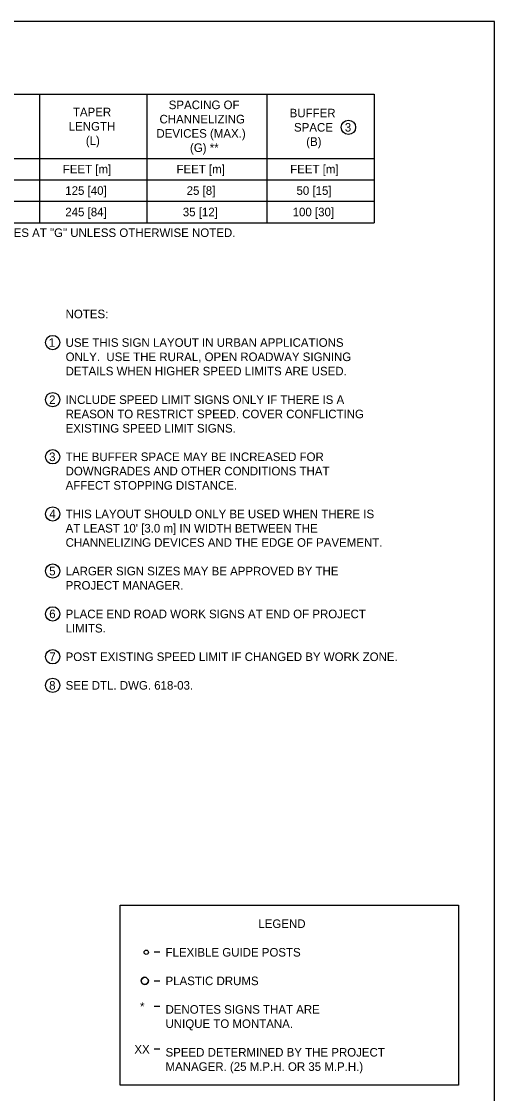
# Model space of a CAD drawing. Extents: x 49991.4 to 50021, y 49987.6 to 50011.4.
# Drawn here: x 50005.31 to 50008.61, y 50003.76 to 50011.26 of the extents above; entities that cross this region are included whole.
import ezdxf

# ---------------------------------------------------------------- set-up
doc = ezdxf.new("R2010")
doc.units = 0
doc.layers.add('Level 1', color=7, linetype='Continuous')
doc.layers.add('Level 2', color=7, linetype='Continuous')

msp = doc.modelspace()

# ---------------------------------------------------------------- linework, layer by layer
at = {"layer": 'Level 1'}
msp.add_lwpolyline([(50008.6146, 50011.2628), (50000.3356, 50011.2628), (50000.3356, 50000.0624), (50008.6146, 50000.0624)], close=True, dxfattribs=at)
for centre, radius in [((50006.1788, 50004.7458), 0.015), ((50006.1688, 50004.5458), 0.025)]:
    msp.add_circle(centre, radius, dxfattribs=at)
for start, end in [(360, 180), (180, 0)]:
    msp.add_arc((50006.1688, 50004.5458), 0.025, start, end, dxfattribs=at)
at = {"layer": 'Level 2'}
for p, q in [((50003.8428, 50010.7538), (50007.7728, 50010.7538)), ((50005.4328, 50010.7538), (50005.4328, 50009.8538)), ((50006.1828, 50010.7538), (50006.1828, 50009.8538)), ((50007.0228, 50010.7538), (50007.0228, 50009.8538)), ((50007.7728, 50010.7538), (50007.7728, 50009.8538)), ((50003.8428, 50010.3038), (50007.7728, 50010.3038)), ((50003.8428, 50010.1538), (50007.7728, 50010.1538)), ((50003.8428, 50010.0038), (50007.7728, 50010.0038)), ((50003.8428, 50009.8538), (50007.7728, 50009.8538)), ((50005.996, 50003.8158), (50005.996, 50005.0758)), ((50006.2738, 50004.7458), (50006.2338, 50004.7458)), ((50006.2338, 50004.5458), (50006.2738, 50004.5458)), ((50006.2738, 50004.3666), (50006.2338, 50004.3666)), ((50006.2738, 50004.0666), (50006.2338, 50004.0666)), ((50008.3627, 50003.8158), (50005.996, 50003.8158))]:
    msp.add_line(p, q, dxfattribs=at)
msp.add_lwpolyline([(50005.996, 50005.0758), (50008.3627, 50005.0758), (50008.3627, 50003.8158)], dxfattribs=at)
for centre in [(50007.5928, 50010.5216), (50005.5249, 50009.0148), (50005.5249, 50008.6148), (50005.5249, 50008.2148), (50005.5249, 50007.8148), (50005.5249, 50007.4148), (50005.5249, 50007.1148), (50005.5249, 50006.8148), (50005.5249, 50006.6148)]:
    msp.add_circle(centre, 0.0501, dxfattribs=at)

# ---------------------------------------------------------------- texts
for s, p in [('TAPER', (50005.6661, 50010.5988)), ('SPACING OF', (50006.3363, 50010.6488)), ('BUFFER', (50007.1817, 50010.5915)), ('CHANNELIZING', (50006.2716, 50010.5488)), ('LENGTH', (50005.6369, 50010.4988)), ('DEVICES (MAX.)', (50006.2502, 50010.4488)), ('SPACE', (50007.2125, 50010.4915)), ('3', (50007.5676, 50010.4916)), ('(L)', (50005.7562, 50010.3988)), ('(B)', (50007.2977, 50010.3915)), ('(G) **', (50006.4849, 50010.3488)), ('FEET [m]', (50005.5955, 50010.1988)), ('FEET [m]', (50006.3905, 50010.1988)), ('FEET [m]', (50007.1855, 50010.1988)), ('125 [40]', (50005.6127, 50010.0488)), ('25 [8]', (50006.4615, 50010.0488)), ('50 [15]', (50007.2296, 50010.0488)), ('245 [84]', (50005.6127, 50009.8988)), ('35 [12]', (50006.4346, 50009.8988)), ('100 [30]', (50007.2027, 50009.8988)), ('** SPACE ALL CHANNELIZING DEVICES AT "G" UNLESS OTHERWISE NOTED.', (50003.8428, 50009.7538)), ('NOTES:', (50005.615, 50009.1848)), ('1', (50005.4967, 50008.9848)), ('USE THIS SIGN LAYOUT IN URBAN APPLICATIONS', (50005.615, 50008.9848)), ('ONLY.  USE THE RURAL, OPEN ROADWAY SIGNING ', (50005.615, 50008.8848)), ('DETAILS WHEN HIGHER SPEED LIMITS ARE USED.', (50005.615, 50008.7848)), ('2', (50005.4998, 50008.5848)), ('INCLUDE SPEED LIMIT SIGNS ONLY IF THERE IS A', (50005.615, 50008.5848)), ('REASON TO RESTRICT SPEED. COVER CONFLICTING', (50005.615, 50008.4848)), ('EXISTING SPEED LIMIT SIGNS.', (50005.615, 50008.3848)), ('3', (50005.4997, 50008.1848)), ('THE BUFFER SPACE MAY BE INCREASED FOR', (50005.615, 50008.1848)), ('DOWNGRADES AND OTHER CONDITIONS THAT', (50005.615, 50008.0848)), ('AFFECT STOPPING DISTANCE.', (50005.615, 50007.9848)), ('4', (50005.501, 50007.7848)), ('THIS LAYOUT SHOULD ONLY BE USED WHEN THERE IS', (50005.615, 50007.7848)), ("AT LEAST 10' [3.0 m] IN WIDTH BETWEEN THE ", (50005.615, 50007.6848)), ('CHANNELIZING DEVICES AND THE EDGE OF PAVEMENT.', (50005.615, 50007.5848)), ('5', (50005.5, 50007.3848)), ('LARGER SIGN SIZES MAY BE APPROVED BY THE', (50005.615, 50007.3848)), ('PROJECT MANAGER.', (50005.615, 50007.2848)), ('6', (50005.5004, 50007.0848)), ('PLACE END ROAD WORK SIGNS AT END OF PROJECT', (50005.615, 50007.0848)), ('LIMITS.', (50005.615, 50006.9848)), ('7', (50005.5011, 50006.7848)), ('POST EXISTING SPEED LIMIT IF CHANGED BY WORK ZONE.', (50005.615, 50006.7848)), ('8', (50005.5, 50006.5848)), ('SEE DTL. DWG. 618-03.', (50005.615, 50006.5848)), ('LEGEND', (50006.963, 50004.9158)), ('FLEXIBLE GUIDE POSTS', (50006.3138, 50004.7158)), ('PLASTIC DRUMS', (50006.3138, 50004.5158)), ('*', (50006.1352, 50004.3366)), ('DENOTES SIGNS THAT ARE', (50006.3138, 50004.3158)), ('UNIQUE TO MONTANA.', (50006.3138, 50004.2158)), ('XX', (50006.096, 50004.0366)), ('SPEED DETERMINED BY THE PROJECT', (50006.3138, 50004.0158)), ('MANAGER. (25 M.P.H. OR 35 M.P.H.)', (50006.3138, 50003.9158))]:
    msp.add_text(s, height=0.06, dxfattribs=at).set_placement(p)

doc.saveas('drawing.dxf')
